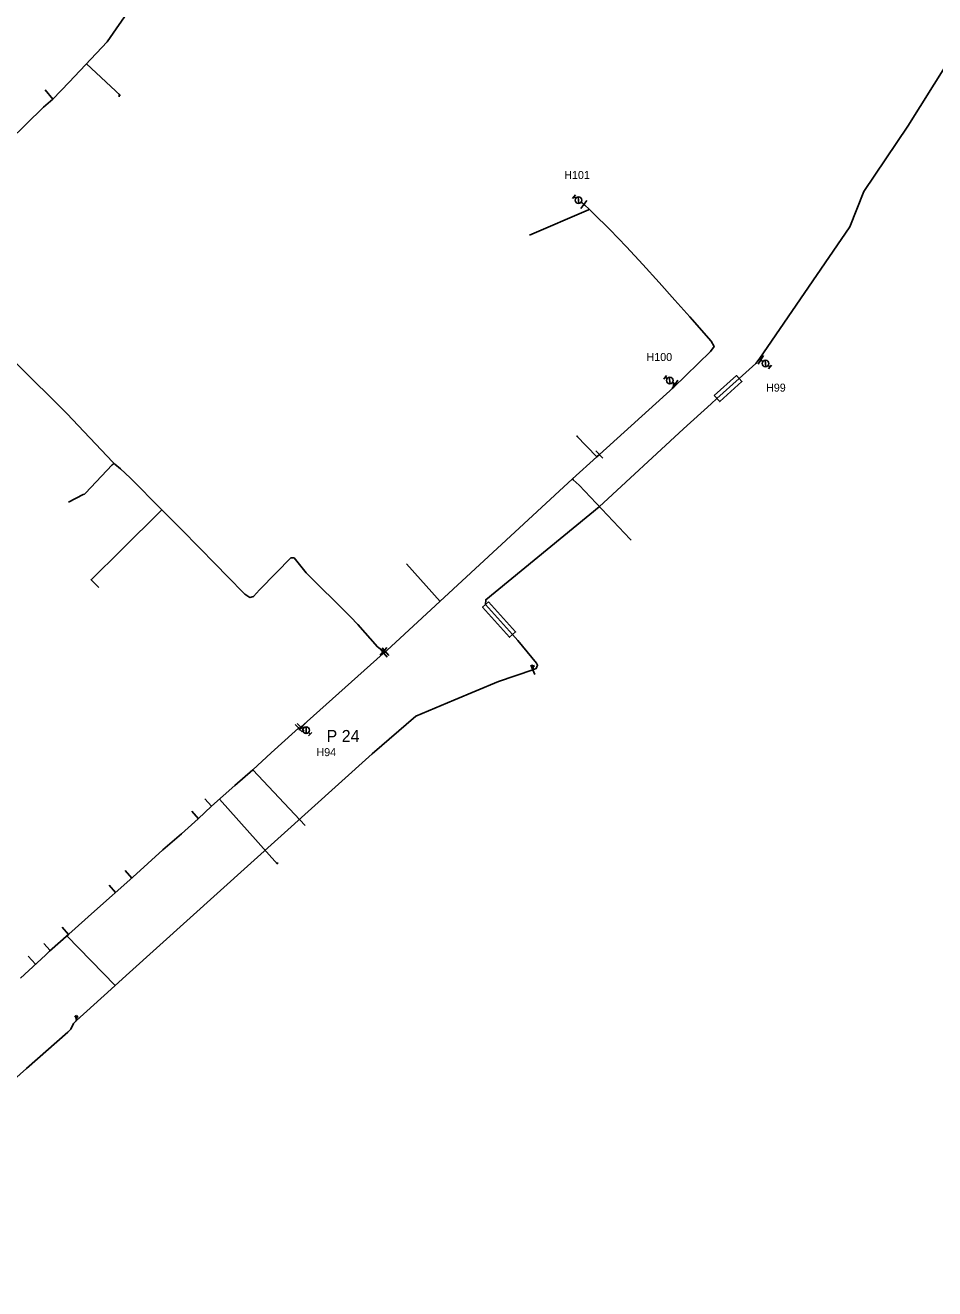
# Model space of a CAD drawing. Extents: x -548873 to -538270, y -1201997 to -1192514.
# Drawn here: x -544691.4 to -544463.9, y -1193768.7 to -1193452.8 of the extents above; entities that cross this region are included whole.
import ezdxf

# ---------------------------------------------------------------- set-up
doc = ezdxf.new("R2010")
doc.units = 0
for name, color, linetype in [('KN_HRAN_STÁTNÍ', 7, 'Continuous'), ('KN_PARC_Č', 7, 'Continuous'), ('KN_VKP_HRAN_SPORNÁ', 7, 'Continuous'), ('PK_PARC_Čv', 7, 'Continuous'), ('Vrstva 29', 7, 'Continuous'), ('Vrstva 37', 7, 'Continuous'), ('Vrstva 39', 7, 'Continuous')]:
    doc.layers.add(name, color=color, linetype=linetype)

# ---------------------------------------------------------------- blocks, each defined once
blk = doc.blocks.new('160')
at = {"layer": 'KN_HRAN_STÁTNÍ'}
blk.add_circle((0, 0), 0.0458, dxfattribs=at)
blk = doc.blocks.new('147')
at = {"layer": 'KN_HRAN_STÁTNÍ'}
blk.add_line((0, 1.27), (0, -1.27), dxfattribs=at)
blk = doc.blocks.new('133')
at = {"layer": 'KN_HRAN_STÁTNÍ'}
for p, q in [((0.28, 0), (0, 0)), ((0.54, 0.58), (1.7, -0.58)), ((1.94, 0), (2.52, 0)), ((2.52, 0.58), (2.52, -0.58))]:
    blk.add_line(p, q, dxfattribs=at)
blk.add_circle((1.11, 0), 0.825, dxfattribs=at)
blk = doc.blocks.new('150')
at = {"layer": 'KN_HRAN_STÁTNÍ'}
blk.add_line((0, 1.27), (0, -1.27), dxfattribs=at)
blk = doc.blocks.new('124')
at = {"layer": 'KN_HRAN_STÁTNÍ'}
for q in [(-0.19, 1.22), (-0.19, 0.92), (0.19, 1.22), (0, 0), (0.19, 0.92)]:
    blk.add_line((0, 1.07), q, dxfattribs=at)
blk = doc.blocks.new('128')
at = {"layer": 'KN_HRAN_STÁTNÍ'}
for p, q in [((-0.19, 1.06), (-0.43, 1.15)), ((-0.36, 0.84), (-0.19, 1.06)), ((-0.19, 1.06), (-0.02, 1.25)), ((-0.19, 1.06), (0, 0)), ((0.05, 0.95), (-0.19, 1.06)), ((-0.1, 1), (0.41, 0.91)), ((-0.07, 0.82), (0.17, 0.96)), ((0.17, 0.96), (-0.02, 1.13)), ((0.17, 0.96), (0, 0)), ((0.19, 1.21), (0.17, 0.96)), ((0.17, 0.96), (0.38, 1.08)), ((0.36, 0.77), (0.17, 0.96))]:
    blk.add_line(p, q, dxfattribs=at)

msp = doc.modelspace()

# ---------------------------------------------------------------- linework, layer by layer
at = {"layer": 'KN_PARC_Č'}
for points in [[(-544676.042, -1193462.423), (-544667.529, -1193470.383)], [(-544684.479, -1193471.289), (-544686.341, -1193468.954)], [(-544667.901, -1193470.036), (-544667.903, -1193470.696)], [(-544550.32, -1193498.8), (-544550.46, -1193498.95), (-544565.269, -1193505.303)], [(-544548.39, -1193560.706), (-544553.47, -1193555.49)], [(-544553.337, -1193555.627), (-544553.202, -1193555.47)], [(-544669.19, -1193562.31), (-544669.28, -1193562.42), (-544669.41, -1193562.56), (-544669.64, -1193562.72), (-544676.25, -1193569.78), (-544676.58, -1193570.02), (-544676.91, -1193570.1), (-544680.514, -1193572.019)], [(-544554.53, -1193566.24), (-544554.35, -1193566.41), (-544552.87, -1193567.82), (-544540.07, -1193581.25), (-544539.784, -1193581.56)], [(-544657.211, -1193573.933), (-544657.44, -1193574.16), (-544667.3, -1193583.94), (-544674.899, -1193591.411), (-544672.956, -1193593.388)], [(-544587.618, -1193596.839), (-544596.034, -1193587.447)], [(-544634.427, -1193638.955), (-544621.374, -1193652.885)], [(-544644.749, -1193648.051), (-544646.43, -1193646.163)], [(-544642.791, -1193646.296), (-544628.258, -1193662.523)], [(-544648.062, -1193651.185), (-544649.738, -1193649.316)], [(-544628.468, -1193662.289), (-544628.099, -1193662.293)], [(-544664.67, -1193665.992), (-544666.37, -1193664.091)], [(-544668.764, -1193669.615), (-544670.376, -1193667.807)], [(-544680.529, -1193680.107), (-544682.157, -1193678.3)], [(-544685.113, -1193684.145), (-544686.71, -1193682.35)], [(-544680.929, -1193680.459), (-544668.871, -1193692.832)], [(-544688.833, -1193687.56), (-544690.612, -1193685.571)]]:
    msp.add_lwpolyline(points, dxfattribs=at)
at = {"layer": 'KN_VKP_HRAN_SPORNÁ'}
for points in [[(-544618.32, -1193373.547), (-544618.82, -1193374.46), (-544619.09, -1193374.97), (-544620.49, -1193377.221), (-544637.21, -1193404.11), (-544643.44, -1193413.61), (-544645.44, -1193416.9), (-544646.687, -1193418.924), (-544662.3, -1193444.264), (-544665.07, -1193448.54), (-544670.89, -1193456.94), (-544680.37, -1193467.03), (-544684.479, -1193471.289), (-544686.79, -1193473.29), (-544703.94, -1193490), (-544709.66, -1193495.02)], [(-544564.42, -1193613.96), (-544563.58, -1193613.64), (-544563.23, -1193612.82), (-544563.46, -1193612.26), (-544568.15, -1193606.62), (-544569.48, -1193605.14), (-544576.26, -1193597.64), (-544576.2, -1193596.41), (-544547.81, -1193573.2), (-544526.73, -1193553.67), (-544519.797, -1193547.433), (-544518.36, -1193546.14), (-544512.78, -1193541.12), (-544508.62, -1193537.35), (-544507.81, -1193536.27), (-544485.11, -1193503.2), (-544481.67, -1193494.36), (-544470.62, -1193478.04), (-544460.97, -1193462.61)], [(-544524.58, -1193526.34), (-544525.12, -1193525.74), (-544528.89, -1193521.5), (-544532.85, -1193517.11), (-544536.87, -1193512.61), (-544540.96, -1193508.23), (-544545.12, -1193503.91), (-544549.3, -1193499.76), (-544550.32, -1193498.8), (-544551.437, -1193497.791)], [(-544529.225, -1193543.354), (-544519.956, -1193534.388), (-544519.077, -1193533.156), (-544519.808, -1193531.786), (-544524.58, -1193526.34)], [(-544693.61, -1193537.3), (-544680.95, -1193549.85), (-544669.47, -1193562.02), (-544669.19, -1193562.31), (-544668.92, -1193562.54), (-544667.56, -1193563.72), (-544665.13, -1193565.99), (-544657.211, -1193573.933), (-544652.24, -1193578.92), (-544643.66, -1193587.64), (-544640.83, -1193590.56), (-544636.43, -1193595.05), (-544635.19, -1193595.84), (-544634.26, -1193595.61), (-544632.75, -1193593.92), (-544628.63, -1193589.72), (-544624.92, -1193585.93), (-544624.12, -1193585.95), (-544621.07, -1193589.67), (-544610.47, -1193600.3), (-544610.01, -1193600.72), (-544608.159, -1193602.639), (-544603.24, -1193608.16), (-544602.58, -1193608.7), (-544602.1, -1193609.08), (-544601.75, -1193609.34)], [(-544547.77, -1193560.14), (-544529.225, -1193543.354)], [(-544601.262, -1193609.434), (-544600.93, -1193609.15), (-544554.53, -1193566.24), (-544548.389, -1193560.705), (-544547.77, -1193560.14)], [(-544622.461, -1193628.279), (-544601.82, -1193609.89), (-544601.686, -1193609.785)], [(-544601.75, -1193609.34), (-544601.49, -1193609.63)], [(-544601.686, -1193609.785), (-544601.49, -1193609.63)], [(-544601.49, -1193609.63), (-544601.262, -1193609.434)], [(-544678.562, -1193701.598), (-544669.91, -1193693.8), (-544666.083, -1193690.351), (-544604.58, -1193634.93), (-544593.65, -1193625.52), (-544584.151, -1193621.551), (-544572.97, -1193616.88), (-544564.42, -1193613.96)], [(-544622.991, -1193628.539), (-544623.869, -1193629.299), (-544629.84, -1193634.74), (-544634.41, -1193638.94), (-544638.96, -1193642.86), (-544644.77, -1193648.07), (-544648.12, -1193651.24), (-544652.32, -1193654.96), (-544656.94, -1193658.93), (-544664.43, -1193665.78), (-544674.08, -1193674.32), (-544680.43, -1193680.02), (-544685.3, -1193684.31), (-544686.327, -1193685.256), (-544692.588, -1193691.012)], [(-544622.966, -1193628.516), (-544622.991, -1193628.539)], [(-544622.966, -1193628.516), (-544622.834, -1193628.62), (-544622.461, -1193628.279)], [(-544753.19, -1193768.67), (-544752.199, -1193767.805), (-544751.7, -1193767.37), (-544749.99, -1193765.72), (-544745.49, -1193761.67), (-544736.98, -1193754.24), (-544736.11, -1193753.94), (-544725.23, -1193744.44), (-544714.9, -1193735.03), (-544711.92, -1193732.21), (-544691.02, -1193713.6), (-544680.67, -1193704.51), (-544679.98, -1193703.76), (-544679.27, -1193702.36), (-544678.562, -1193701.598)]]:
    msp.add_lwpolyline(points, dxfattribs=at)
at = {"layer": 'PK_PARC_Čv'}
for points in [[(-544551.437, -1193497.791), (-544551.66, -1193497.59), (-544552.12, -1193497.22)], [(-544507.81, -1193536.27), (-544507.43, -1193536.46), (-544507.12, -1193536.7)], [(-544528.595, -1193542.745), (-544529.263, -1193542.271)], [(-544622.186, -1193628.034), (-544621.93, -1193628.29)]]:
    msp.add_lwpolyline(points, dxfattribs=at)
at = {"layer": 'Vrstva 37'}
for points in [[(-544519.029, -1193545.397), (-544513.449, -1193540.377), (-544512.111, -1193541.863), (-544517.691, -1193546.883), (-544519.029, -1193545.397)], [(-544575.518, -1193596.969), (-544568.738, -1193604.469), (-544570.222, -1193605.811), (-544577.002, -1193598.311), (-544575.518, -1193596.969)]]:
    msp.add_lwpolyline(points, dxfattribs=at)

# ---------------------------------------------------------------- block references
at = {"layer": 'PK_PARC_Čv'}
for name, p, xscale, yscale, rotation in [('133', (-544552.12, -1193497.22), 1.000000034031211, 1.0000000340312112, 141.99999959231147), ('150', (-544551.66, -1193497.59), 1.000000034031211, 1.0000000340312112, -38.000000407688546), ('150', (-544507.43, -1193536.46), 0.9999999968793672, 0.9999999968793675, -32.00000027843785), ('133', (-544507.12, -1193536.7), 0.9999999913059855, 0.9999999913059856, -37.00000193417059), ('133', (-544529.263, -1193542.271), 1.000000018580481, 1.000000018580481, 144.99999976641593), ('150', (-544528.846, -1193542.567), 1.000000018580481, 1.000000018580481, -35.000000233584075), ('150', (-544622.079, -1193628.141), 1.0000000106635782, 1.0000000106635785, -44.00000165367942), ('133', (-544621.93, -1193628.29), 1.0000000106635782, 1.0000000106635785, -44.00000165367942)]:
    msp.add_blockref(name, p, dxfattribs=dict(at, xscale=xscale, yscale=yscale, rotation=rotation))
at = {"layer": 'Vrstva 29'}
for name, p, xscale, yscale, rotation in [('160', (-544551.437, -1193497.791), 1.0000000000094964, 1.0000000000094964, 137.9999986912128), ('160', (-544524.58, -1193526.34), 1.0000000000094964, 1.0000000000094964, -47.99999869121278), ('160', (-544529.225, -1193543.354), 1.0000000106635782, 1.0000000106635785, 44.00000165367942), ('147', (-544547.77, -1193560.14), 1.00000000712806, 1.00000000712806, -136.99999943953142), ('147', (-544601.75, -1193609.34), 1.0000000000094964, 1.0000000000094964, 137.9999986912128), ('147', (-544601.686, -1193609.785), 1.000000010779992, 1.0000000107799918, -141.00000108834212), ('147', (-544601.262, -1193609.434), 1.0000000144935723, 1.0000000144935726, -139.00000089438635), ('160', (-544601.49, -1193609.63), 1.0002788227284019, 1.0002788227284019, 176.70930040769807), ('147', (-544564.42, -1193613.96), 1.0296949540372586, 1.0296949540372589, -155.86620948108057), ('147', (-544622.991, -1193628.539), 1.0000000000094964, 1.0000000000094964, -137.9999986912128), ('147', (-544622.461, -1193628.279), 1.00000000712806, 1.00000000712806, -136.99999943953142), ('160', (-544622.966, -1193628.516), 1.00000001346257, 1.0000000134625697, -178.0000000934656), ('160', (-544678.562, -1193701.598), 0.999999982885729, 0.9999999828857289, 135)]:
    msp.add_blockref(name, p, dxfattribs=dict(at, xscale=xscale, yscale=yscale, rotation=rotation))
at = {"layer": 'Vrstva 39'}
for name, p in [('124', (-544529.225, -1193543.354)), ('128', (-544564.42, -1193613.96)), ('128', (-544678.562, -1193701.598))]:
    msp.add_blockref(name, p, dxfattribs=at)

# ---------------------------------------------------------------- texts
at = {"layer": 'PK_PARC_Čv'}
for s, height, p in [('H101', 2, (-544556.55, -1193491.25)), ('H100', 2, (-544535.973, -1193536.741)), ('H99', 2, (-544506.08, -1193544.4)), ('P 24', 3, (-544616.01, -1193631.99)), ('H94', 2, (-544618.53, -1193635.53))]:
    msp.add_text(s, height=height, dxfattribs=at).set_placement(p)

doc.saveas('drawing.dxf')
